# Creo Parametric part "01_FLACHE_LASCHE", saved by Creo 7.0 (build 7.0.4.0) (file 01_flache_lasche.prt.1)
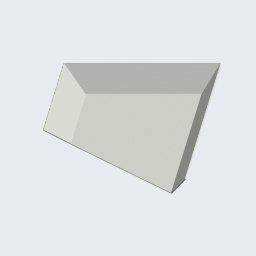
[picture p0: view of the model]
Units: millimeter Kilogram Sec (mmKs); MM, KILOGRAM, SECS
Materials in the file: S235JRG2

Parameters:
  SMT_PART_BEND_ALLOW_FACTOR_TYPE = "Y FACTOR"
  SMT_DFLT_RADIUS_SIDE = "Inside"
  SMT_DFLT_CRNR_REL_TYPE = "V Notch"
  SMT_DFLT_CRNR_REL_DEPTH_TYPE = "Blind"
  SMT_DFLT_BEND_REL_TYPE = "Rip"
  SMT_DFLT_BEND_REL_DEPTH_TYPE = "Up to Bend"
  SMT_DFLT_EDGE_TREA_TYPE = "Open"
  PTC_MATERIAL_NAME = "S235JRG2"
  BENENNUNG = "XXX"
  DATUM = "XX.XX.XX"
  ERSTELLER = "ARINDA"
  TEILETYP = "Fertigungsteil"
  SELECT_EN_NAME = "S235JRG2"
  SELECT_DIN_NAME = "RSt37-2"
  SELECT_DIN_NUMBER = "1.0038"
  SELECT_ASTM_NAME = "A 283 M Grade 2"
  MATERIAL_GROUP = "ME_ST_Baustahl"
  STANDARD_EN_DELIVERYSPEC = "DIN EN 10025"
  STANDARD_DIN_DELIVERYSPEC = "DIN 17100"

Other parameters: SMT_THICKNESS, SMT_PART_BEND_ALLOWANCE_FACTOR, SMT_UPDATE_BEND_ALLOW_INFO, SMT_DFLT_BEND_RADIUS, SMT_DFLT_BEND_ANGLE, SMT_DFLT_CRNR_REL_WIDTH, SMT_DFLT_CRNR_REL_DEPTH, SMT_DFLT_BEND_REL_WIDTH, SMT_DFLT_BEND_REL_DEPTH, SMT_DFLT_BEND_REL_ANGLE, SMT_GAP, SMT_DFLT_EDGE_TREA_WIDTH, SMT_DFLT_MITER_CUT_WIDTH, SMT_DFLT_MITER_CUT_OFFSET, MASSE, SMT_DFLT_BEND_REL_LENGTH, D10, D12, D13, D14, D15, D16, D17, D18, D19, D20, D22, D25, D30

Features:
  1. coordinate system
  2. datum plane "DTM1", "T_RECHTS_Y-Z"
  3. datum plane "DTM2", "T_OBEN_X-Z"
  4. datum plane "DTM3", "T_VORNE_X-Y"
  5. datum axis "A_1"
  6. datum axis "A_2"
  7. datum axis "A_3"
  8. fill "Planar 1(Erste Lasche)"
  9. feature "Flange 1"
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
Other named items: T_BASIS, A_X-ACHSE, A_Y-ACHSE, A_Z-ACHSE

Layers: 00_STD-ACHSEN, 00_STD-EBENEN, 00_STD-KOORDSYS, KURVENELEMENTE, SAMMELFLÄCHEN, VOLUMENGEOMETRIE

Notes: V-Ausklinkung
